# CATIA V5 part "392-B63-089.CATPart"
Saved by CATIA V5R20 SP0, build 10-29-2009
Part number: 392-B63-089
Definition: NONE
Nomenclature: 392-B63-089
Source: Unknown
Description: 392-B63-089
Bounding box of the stored display mesh (mm): x 0 to 89, y -31.428 to 31.428, z -31.1 to 31.1
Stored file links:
  C:\Users\Utente\Desktop\IO LAVORO\3D X SITO CF\X SITO\3D files 392B\392-B63-089.CATPart
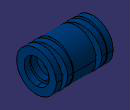
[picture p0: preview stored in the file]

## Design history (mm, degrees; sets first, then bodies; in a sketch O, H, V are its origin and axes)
Body1 "392-B63-089" (main body)
  Solid1: solid without history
